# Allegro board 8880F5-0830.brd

Outline 581.66 x 429.26 mm; copper layers: TOP, L02_DGND, L03_SIGNAL, L04_DGND, L05_SIGNAL, L06_DGND, L07_SIGNAL, L08_DGND, L09_SIGNAL, L10_DGND, L11_POWER, L12_DGND, L13_POWER, L14_DGND, L15_POWER, L16_DGND, L17_5V, L18_CBIT, L19_DGND, L20_POWER, L21_DGND, L22_POWER, L23_DGND, L24_POWER, L25_DGND, L26_SIGNAL, L27_DGND, L28_SIGNAL, L29_DGND, L30_SIGNAL, L31_DGND, L32_SIGNAL, L33_DGND, BOTTOM. Coordinates in mm from the lower left corner of the outline.

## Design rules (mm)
net group DIFFPAIR0: nets D31702 D31704
net group DIFFPAIR1: nets D31706 D31708
net group DIFFPAIR2: nets D31710 D31712
net group DIFFPAIR3: nets D31714 D31716
net group DIFFPAIR4: nets D32102 D32104
net group DIFFPAIR5: nets D32106 D32108
net group DIFFPAIR6: nets D32110 D32112
net group DIFFPAIR7: nets D32114 D32116
net group DIFFPAIR8: nets D30102 D30104
net group DIFFPAIR9: nets D30106 D30108
net group DIFFPAIR10: nets D30110 D30112
net group DIFFPAIR11: nets D30114 D30116
net group DIFFPAIR12: nets D30502 D30504
net group DIFFPAIR13: nets D30506 D30508
net group DIFFPAIR14: nets D30510 D30512
net group DIFFPAIR15: nets D30514 D30516

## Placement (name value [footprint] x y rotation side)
BD29  BD120-3A-S8  [FB0805]  129.54 134.62 180 bottom
BD30  BD120-3A-S8  [FB0805]  129.54 146.05 180 bottom
BD31  BD120-3A-S8  [FB0805]  129.54 142.24 0 bottom
BD32  BD120-3A-S8  [FB0805]  513.08 238.76 180 bottom
BD33  BD120-3A-S8  [FB0805]  513.08 242.57 180 bottom
BD34  BD120-3A-S8  [FB0805]  453.64 145.54 0 bottom
BD35  BD120-3A-S8  [FB0805]  453.64 137.92 180 bottom
BD36  BD120-3A-S8  [FB0805]  129.54 138.43 180 bottom
BD37  BD120-3A-S8  [FB0805]  453.64 130.3 180 bottom
BD38  BD120-3A-S8  [FB0805]  513.08 242.57 180 bottom
BD39  BD120-3A-S8  [FB0805]  453.64 141.73 0 bottom
BD40  BD120-3A-S8  [FB0805]  453.64 134.11 180 bottom
BD41  BD120-3A-S8  [FB0805]  513.08 234.95 180 bottom
BD42  BD120-3A-S8  [FB0805]  513.08 231.14 180 bottom
BD43  BD120-3A-S8  [FB0805]  513.08 227.33 180 bottom
BD44  BD120-3A-S8  [FB0805]  129.54 149.86 180 bottom
BR902  330-1-S4  [R0402]  36.83 133.35 270 bottom
C3  0.1U-16-X-S4-MU  [C0402]  184.15 132.33 180 bottom
C4  0.1U-16-X-S4-MU  [C0402]  181.61 132.33 180 bottom
C5  22P-50-N-S4-AVX  [C0402]  221.21 277.48 90 bottom
C6  22P-50-N-S4-AVX  [C0402]  221.21 271.16 270 bottom
C7  0.1U-16-X-S4-MU  [C0402]  110.74 230.12 0 bottom
C8  0.1U-16-X-S4-MU  [C0402]  104.14 215.5 180 bottom
C9  0.1U-16-X-S4-MU  [C0402]  104.24 229.1 180 bottom
CA1  NC/10U-10-X6S-S6-MU  [C0603]  186.05 292.1 0 bottom
CA2  NC/47U-10-X5R-S8-TDK  [C0805]  186.16 294 0 bottom
CA3  NC/10U-10-X6S-S6-MU  [C0603]  174.62 292.1 180 bottom
CA4  NC/47U-10-X5R-S8-TDK  [C0805]  174.52 294 180 bottom
CA5  NC/10U-10-X6S-S6-MU  [C0603]  117.47 290.83 180 bottom
CA6  NC/47U-10-X5R-S8-TDK  [C0805]  117.37 292.74 180 bottom
CA7  NC/10U-10-X6S-S6-MU  [C0603]  169.54 292.1 0 bottom
CA8  NC/47U-10-X5R-S8-TDK  [C0805]  169.65 294 0 bottom
CA9  NC/10U-10-X6S-S6-MU  [C0603]  158.11 292.1 180 bottom
CA10  NC/47U-10-X5R-S8-TDK  [C0805]  158.01 294 180 bottom
CA11  NC/10U-10-X6S-S6-MU  [C0603]  186.05 275.59 0 bottom
CA12  NC/47U-10-X5R-S8-TDK  [C0805]  186.16 277.5 0 bottom
CA13  NC/47U-10-X5R-S8-TDK  [C0805]  202.16 294 0 bottom
CA14  NC/10U-10-X6S-S6-MU  [C0603]  202.06 292.1 0 bottom
CA15  NC/47U-10-X5R-S8-TDK  [C0805]  190.53 294 180 bottom
CA16  NC/10U-10-X6S-S6-MU  [C0603]  190.63 292.1 180 bottom
CA17  NC/47U-10-X5R-S8-TDK  [C0805]  169.65 277.5 0 bottom
CA18  NC/10U-10-X6S-S6-MU  [C0603]  169.54 275.59 0 bottom
CA19  NC/47U-10-X5R-S8-TDK  [C0805]  100.34 249.52 180 bottom
CA20  NC/10U-10-X6S-S6-MU  [C0603]  100.44 247.61 180 bottom
CA21  10U-10-X6S-S6-MU  [C0603]  186.05 289.56 0 bottom
CA22  10U-10-X6S-S6-MU  [C0603]  174.62 289.56 180 bottom
CA23  10U-10-X6S-S6-MU  [C0603]  117.47 288.29 180 bottom
CA24  10U-10-X6S-S6-MU  [C0603]  169.54 289.56 0 bottom
CA25  10U-10-X6S-S6-MU  [C0603]  158.11 289.56 180 bottom
CA26  10U-10-X6S-S6-MU  [C0603]  186.05 273.05 0 bottom
CA27  10U-10-X6S-S6-MU  [C0603]  202.06 289.56 0 bottom
CA28  10U-10-X6S-S6-MU  [C0603]  190.63 289.56 180 bottom
CA29  10U-10-X6S-S6-MU  [C0603]  169.54 273.05 0 bottom
CA30  NC/47U-10-X5R-S8-TDK  [C0805]  95.47 249.57 180 bottom
CA31  10U-10-X6S-S6-MU  [C0603]  95.57 247.66 180 bottom
CA32  NC/10U-10-X6S-S6-MU  [C0603]  202.06 275.59 0 bottom
CA33  NC/47U-10-X5R-S8-TDK  [C0805]  202.16 277.5 0 bottom
CA34  10U-10-X6S-S6-MU  [C0603]  202.06 273.05 0 bottom
CA35  NC/10U-10-X6S-S6-MU  [C0603]  174.62 275.59 180 bottom
CA36  NC/47U-10-X5R-S8-TDK  [C0805]  174.52 277.5 180 bottom
CA37  10U-10-X6S-S6-MU  [C0603]  174.62 273.05 180 bottom
CA38  NC/10U-10-X6S-S6-MU  [C0603]  158.11 275.59 180 bottom
CA39  NC/47U-10-X5R-S8-TDK  [C0805]  158.01 277.5 180 bottom
CA40  10U-10-X6S-S6-MU  [C0603]  158.11 273.05 180 bottom
CB1  0.1U-25-X-S6  [C0603]  116.84 130.81 0 bottom
CB2  10U-16-T-SA  [CODE_A]  116.84 128.27 0 bottom
CB3  0.1U-25-X-S6  [C0603]  472.44 130.81 0 bottom
CB4  10U-16-T-SA  [CODE_A]  472.44 128.27 0 bottom
CB5  0.1U-25-X-S6  [C0603]  556.51 300.99 0 bottom
CB6  10U-16-T-SA  [CODE_A]  556.51 298.45 0 bottom
CB7  0.1U-25-X-S6  [C0603]  223.52 298.45 0 bottom
CB8  10U-16-T-SA  [CODE_A]  223.52 295.91 0 bottom
CB9  0.1U-25-X-S6  [C0603]  23.01 130.71 0 bottom
CB10  10U-25-X7R-SA  [C1206]  22.86 128.27 0 bottom
CB11  0.1U-25-X-S6  [C0603]  484.02 130.71 0 bottom
CB12  10U-25-X7R-SA  [C1206]  483.87 128.27 0 bottom
CB13  0.1U-25-X-S6  [C0603]  547.52 300.89 0 bottom
CB14  10U-25-X7R-SA  [C1206]  547.37 298.45 0 bottom
CB15  0.1U-25-X-S6  [C0603]  12.45 262.13 0 bottom
CB16  10U-25-X7R-SA  [C1206]  12.3 259.69 0 bottom
CB19  0.1U-25-X7R-S4-MU  [C0402]  215.9 17.78 180 bottom
CC1  0.47U-10-X6S-S2-TY  [C0201]  237.98 224.12 90 bottom
CC2  4.7U-10-X6T-S4-MU  [C0402]  236.32 222.4 270 bottom
CC4  0.47U-10-X6S-S2-TY  [C0201]  229.81 247.93 0 bottom
CC6  0.47U-10-X6S-S2-TY  [C0201]  250.17 224.12 90 bottom
CC7  0.47U-10-X6S-S2-TY  [C0201]  229.81 246.66 0 bottom
CC8  0.47U-10-X6S-S2-TY  [C0201]  263.63 224.12 90 bottom
CC9  0.47U-10-X6S-S2-TY  [C0201]  254.61 266.16 270 bottom
CC11  0.47U-10-X6S-S2-TY  [C0201]  251.06 224.12 90 bottom
CC13  0.47U-10-X6S-S2-TY  [C0201]  256.77 224.12 90 bottom
CC15  4.7U-2.5-X6S-S2-MU  [C0201]  259.65 264.95 90 bottom
CC16  NC/4.7U-2.5-X6S-S2-MU  [C0201]  271.64 249.5 0 bottom
CC17  4.7U-2.5-X6S-S2-MU  [C0201]  229.81 253.69 0 bottom
CC19  0.47U-10-X6S-S2-TY  [C0201]  252.83 266.16 270 bottom
CC20  4.7U-10-X6T-S4-MU  [C0402]  254.11 267.66 0 bottom
CC22  0.47U-10-X6S-S2-TY  [C0201]  251.05 266.16 270 bottom
CC23  4.7U-10-X6T-S4-MU  [C0402]  250.34 253.09 270 bottom
CC25  0.47U-10-X6S-S2-TY  [C0201]  272.85 245.18 180 bottom
CC26  0.47U-10-X6S-S2-TY  [C0201]  253.72 266.16 270 bottom
CC27  0.47U-10-X6S-S2-TY  [C0201]  272.85 249.5 180 bottom
CC28  0.47U-10-X6S-S2-TY  [C0201]  259.65 266.16 270 bottom
CC29  0.47U-10-X6S-S2-TY  [C0201]  231.03 253.69 180 bottom
CC30  0.47U-10-X6S-S2-TY  [C0201]  229.81 243.41 0 bottom
CC31  0.47U-10-X6S-S2-TY  [C0201]  249.28 224.12 90 bottom
CC32  0.47U-10-X6S-S2-TY  [C0201]  262.36 224.12 90 bottom
CC33  0.47U-10-X6S-S2-TY  [C0201]  272.85 243.91 180 bottom
CC34  0.47U-10-X6S-S2-TY  [C0201]  251.94 266.16 270 bottom
CC35  0.47U-10-X6S-S2-TY  [C0201]  272.85 241.37 180 bottom
CC36  0.47U-10-X6S-S2-TY  [C0201]  272.85 242.64 180 bottom
CC37  0.47U-10-X6S-S2-TY  [C0201]  247.57 264.95 90 bottom
CC38  NC/4.7U-2.5-X6S-S2-MU  [C0201]  247.57 266.16 270 bottom
CC39  0.47U-10-X6S-S2-TY  [C0201]  231.03 249.2 180 bottom
CC40  4.7U-2.5-X6S-S2-MU  [C0201]  258.5 246.67 180 bottom
CC41  4.7U-2.5-X6S-S2-MU  [C0201]  229.81 249.2 0 bottom
CC42  4.7U-2.5-X6S-S2-MU  [C0201]  251.54 253.03 90 bottom
CD1  0.1U-10-X7R-S2-MU  [C0201]  237.98 225.34 270 top
CD3  0.1U-10-X7R-S2-MU  [C0201]  271.64 241.37 0 top
CD4  0.1U-10-X7R-S2-MU  [C0201]  254.61 264.95 90 top
CD5  0.1U-10-X7R-S2-MU  [C0201]  263.63 225.34 270 top
CD6  0.1U-10-X7R-S2-MU  [C0201]  231.03 246.66 180 top
CD7  0.1U-10-X7R-S2-MU  [C0201]  271.64 242.64 0 top
CD8  0.1U-10-X7R-S2-MU  [C0201]  251.06 225.34 270 top
CD9  0.1U-10-X7R-S2-MU  [C0201]  256.77 225.34 270 top
CD10  0.1U-10-X7R-S2-MU  [C0201]  271.64 249.5 0 top
CD11  0.1U-10-X7R-S2-MU  [C0201]  259.65 264.95 90 top
CD12  0.1U-10-X7R-S2-MU  [C0201]  231.03 253.69 180 top
CD13  0.1U-10-X7R-S2-MU  [C0201]  252.83 264.95 90 top
CD14  0.1U-10-X7R-S2-MU  [C0201]  251.05 264.95 90 top
CD15  0.1U-10-X7R-S2-MU  [C0201]  271.64 245.18 0 top
CD16  0.1U-10-X7R-S2-MU  [C0201]  253.72 264.95 90 top
CD17  0.1U-10-X7R-S2-MU  [C0201]  231.03 247.93 180 top
CD18  0.1U-10-X7R-S2-MU  [C0201]  251.94 264.95 90 top
CD19  0.1U-10-X7R-S2-MU  [C0201]  231.03 243.41 180 top
CD20  0.1U-10-X7R-S2-MU  [C0201]  271.64 243.91 0 top
CD21  0.1U-10-X7R-S2-MU  [C0201]  262.36 225.34 270 top
CD22  0.1U-10-X7R-S2-MU  [C0201]  249.28 225.34 270 top
CD23  0.1U-10-X7R-S2-MU  [C0201]  250.17 225.34 270 top
CD24  0.1U-10-X7R-S2-MU  [C0201]  247.57 264.95 90 top
CD25  0.1U-10-X7R-S2-MU  [C0201]  231.03 249.2 180 top
CSDPS225  V93K_CSDPS_DPS32  [PG_VG93K_PF_DPS32_G8D225]  254 331.47 0 top
CSDPS229  V93K_CSDPS_DPS32  [PG_VG93K_PF_DPS32_G8D229]  180.34 331.47 0 top
CSDPS425  V93K_CSDPS_DPS32  [PG_VG93K_PF_DPS32_G8D425]  254 341.63 0 top
CSDPS429  V93K_CSDPS_DPS32  [PG_VG93K_PF_DPS32_G8D429]  180.34 341.63 0 top
D101/D501  V93K_PS1600 HD  [PG_VG93K_F_HSM_G1D101_501_ND]  327.66 97.79 0 top
D102  V93K_CH  [PG_VG93K_F_G1D102]  327.66 77.47 0 top
D103  V93K_CH  [PG_VG93K_F_G1D103]  327.66 57.15 0 top
D104  V93K_CH  [PG_VG93K_F_G1D104]  327.66 36.83 0 top
D105/D505  V93K_PS1600 HD  [PG_VG93K_F_HSM_G1D105_505_ND]  401.32 97.79 0 top
D106  V93K_CH  [PG_VG93K_F_G1D106]  401.32 77.47 0 top
D107  V93K_CH  [PG_VG93K_F_G1D107]  401.32 57.15 0 top
D108  V93K_CH  [PG_VG93K_F_G1D108]  401.32 36.83 0 top
D109  V93K_CH  [PG_VG93K_F_G2D109]  401.32 331.47 0 top
D110  V93K_CH  [PG_VG93K_F_G2D110]  401.32 351.79 0 top
D111  V93K_CH  [PG_VG93K_F_G2D111]  401.32 372.11 0 top
D112  V93K_CH  [PG_VG93K_F_G2D112]  401.32 392.43 0 top
D113  V93K_CH  [PG_VG93K_F_G2D113]  327.66 331.47 0 top
D114  V93K_CH  [PG_VG93K_F_G2D114]  327.66 351.79 0 top
D115  V93K_CH  [PG_VG93K_F_G2D115]  327.66 372.11 0 top
D116  V93K_CH  [PG_VG93K_F_G2D116]  327.66 392.43 0 top
D117/D517  V93K_PS1600 HD  [PG_VG93K_F_HSM_G3D117_517_ND]  180.34 97.79 0 top
D118  V93K_CH  [PG_VG93K_F_G3D118]  180.34 77.47 0 top
D119  V93K_CH  [PG_VG93K_F_G3D119]  180.34 57.15 0 top
D120  V93K_CH  [PG_VG93K_F_G3D120]  180.34 36.83 0 top
D121/D521  V93K_PS1600 HD  [PG_VG93K_F_HSM_G3D121_521_ND]  254 97.79 0 top
D122  V93K_CH  [PG_VG93K_F_G3D122]  254 77.47 0 top
D123  V93K_CH  [PG_VG93K_F_G3D123]  254 57.15 0 top
D124  V93K_CH  [PG_VG93K_F_G3D124]  254 36.83 0 top
D125  V93K_CH  [PG_VG93K_F_G4D125]  33.02 97.79 0 top
D126  V93K_CH  [PG_VG93K_F_G4D126]  33.02 77.47 0 top
D127  V93K_CH  [PG_VG93K_F_G4D127]  33.02 57.15 0 top
D128  V93K_CH  [PG_VG93K_F_G4D128]  33.02 36.83 0 top
D129  V93K_CH  [PG_VG93K_F_G4D129]  106.68 97.79 0 top
D130  V93K_CH  [PG_VG93K_F_G4D130]  106.68 77.47 0 top
D131  V93K_CH  [PG_VG93K_F_G4D131]  106.68 57.15 0 top
D132  V93K_CH  [PG_VG93K_F_G4D132]  106.68 36.83 0 top
D231  V93K_CH  [PG_VG93K_F_G8D231]  180.34 372.11 0 top
D301  V93K_CH  [PG_VG93K_F_G1D301]  327.66 87.63 0 top
D302  V93K_CH  [PG_VG93K_F_G1D302]  327.66 67.31 0 top
D305  V93K_CH  [PG_VG93K_F_G1D305]  401.32 87.63 0 top
D306  V93K_CH  [PG_VG93K_F_G1D306]  401.32 67.31 0 top
D309  V93K_PSSL  [PG_VG93K_F_PSSL_G2D309_ND]  401.32 341.63 0 top
D313  V93K_PSSL  [PG_VG93K_F_PSSL_G2D313_ND]  327.66 341.63 0 top
D317  V93K_CH  [PG_VG93K_F_G3D317]  180.34 87.63 0 top
D318  V93K_CH  [PG_VG93K_F_G3D318]  180.34 67.31 0 top
D321  V93K_CH  [PG_VG93K_F_G3D321]  254 87.63 0 top
D322  V93K_CH  [PG_VG93K_F_G3D322]  254 67.31 0 top
D431  V93K_CH  [PG_VG93K_F_G8D431]  180.34 382.27 0 top
DPS1  V93K_DPS  [PG_VG93K_F_G1DPS1]  401.32 16.51 0 top
DPS2  V93K_DPS  [PG_VG93K_F_G2DPS2]  327.66 412.75 0 top
DPS3  V93K_DPS  [PG_VG93K_F_G3DPS3]  254 16.51 0 top
DPS8  V93K_DPS  [PG_VG93K_F_G8DPS8]  180.34 412.75 0 top
FD1  -  [FD_040_V2]  159.82 131.98 0 top
FD2  -  [FD_040_V2]  423.24 131.98 0 top
FD3  -  [FD_040_V2]  423.24 297.28 0 top
FD4  -  [FD_040_V2]  156.51 297.46 0 top
FD5  -  [FD_040_V2]  159.82 131.98 180 bottom
FD6  -  [FD_040_V2]  423.24 131.98 180 bottom
FD7  -  [FD_040_V2]  423.24 297.28 180 bottom
FD8  -  [FD_040_V2]  156.51 297.46 180 bottom
FD9  -  [FD_040_V2]  570.23 128.27 180 bottom
FD10  -  [FD_040_V2]  570.23 300.99 0 top
FD11  -  [FD_040_V2]  570.23 300.99 180 bottom
FD12  -  [FD_040_V2]  11.43 300.99 0 top
FD13  -  [FD_040_V2]  11.43 300.99 180 bottom
FD14  -  [FD_040_V2]  11.43 127 0 top
FD15  -  [FD_040_V2]  11.43 127 180 bottom
FD16  -  [FD_040_V2]  570.23 128.27 0 top
GND1  TP01  [TP_040_T]  173.57 294 0 top
GND2  TP01  [TP_040_T]  187.11 294 180 top
GND3  TP01  [TP_040_T]  116.42 292.74 0 top
GND4  TP01  [TP_040_T]  157.06 294 0 top
GND5  TP01  [TP_040_T]  170.6 294 180 top
GND6  TP01  [TP_040_T]  173.57 277.5 0 top
GND7  TP01  [TP_040_T]  203.11 294 180 top
GND8  TP01  [TP_040_T]  189.58 294 0 top
GND9  TP01  [TP_040_T]  170.6 277.5 180 top
GND10  TP01  [TP_040_T]  99.36 249.46 0 top
GND11  TP01  [TP_040_T]  94.49 249.52 0 top
GND12  TP01  [TP_040_T]  203.11 277.5 180 top
GND13  TP01  [TP_040_T]  187.11 277.5 180 top
GND14  TP01  [TP_040_T]  157.06 277.5 0 top
HX8880-F05  REF-CODE-CHIP  [CHIP_CODE]  559.05 279.65 0 top
J1  HDR-2X1-M  [JP_2P_100]  110.24 232.41 270 bottom
J2  HDR-3X1-M  [JP_3P_100]  88.76 205.43 90 bottom
J3  HDR-3X1-M  [JP_3P_100]  88.76 219.15 90 bottom
J4  HDR-2X1-M  [JP_2P_100]  96.27 231.39 90 bottom
J5  HDR-2X1-M  [JP_2P_100]  96.27 243.08 90 bottom
JG_220919AA01  REF-CODE-SOCKET  [SOCKET_CODE]  559.05 284.73 0 top
JG_220919AA02  REF-CODE-SOCKET  [SOCKET_CODE]  559.05 287.27 0 top
K1  G6K-2F-RF-T-5V-SPECIAL  [RL_G6K2FRT_8P_5V_GR]  347.73 292.86 0 bottom
K2  G6K-2F-RF-T-5V-SPECIAL  [RL_G6K2FRT_8P_5V_GR]  334.26 292.86 0 bottom
K3  G6K-2F-RF-T-5V-SPECIAL  [RL_G6K2FRT_8P_5V_GR]  320.8 292.86 0 bottom
K4  G6K-2F-RF-T-5V-SPECIAL  [RL_G6K2FRT_8P_5V_GR]  289.56 276.1 180 bottom
K5  G6K-2F-RF-T-5V-SPECIAL  [RL_G6K2FRT_8P_5V_GR]  307.59 292.86 0 bottom
K6  G6K-2F-RF-T-5V-SPECIAL  [RL_G6K2FRT_8P_5V_GR]  294.39 292.86 0 bottom
K7  G6K-2F-RF-T-5V-SPECIAL  [RL_G6K2FRT_8P_5V_GR]  280.92 292.86 0 bottom
K8  G6K-2F-RF-T-5V-SPECIAL  [RL_G6K2FRT_8P_5V_GR]  267.46 292.86 0 bottom
K9  UA2-5NJ-A-V3  [RL_NECUA2_5V_V3]  219.96 235.46 90 bottom
K10  UA2-5NJ-A-V3  [RL_NECUA2_5V_V3]  111.76 237.24 0 bottom
K11  G6K-2F-RF-T-5V-SPECIAL  [RL_G6K2FRT_8P_5V_GR]  254.25 292.86 0 bottom
K12  UA2-5NJ-A-V3  [RL_NECUA2_5V_V3]  219.96 246.89 90 bottom
K13  UA2-5NJ-A-V3  [RL_NECUA2_5V_V3]  123.7 229.62 180 bottom
K14  UA2-5NJ-A-V3  [RL_NECUA2_5V_V3]  112.01 220.73 180 bottom
K15  UA2-5NJ-A-V3  [RL_NECUA2_5V_V3]  123.99 213.19 180 bottom
K16  G6K-2F-RF-T-5V-SPECIAL  [RL_G6K2FRT_8P_5V_GR]  241.05 292.61 180 bottom
K17  G6K-2F-RF-T-5V-SPECIAL  [RL_G6K2FRT_8P_5V_GR]  188.47 260.35 270 bottom
K18  UB2-5NU-B  [RL_NECUB2_5V]  228.45 274.32 0 bottom
K19  UA2-5NJ-A-V3  [RL_NECUA2_5V_V3]  112.01 213.11 180 bottom
K20  UA2-5NJ-A-V3  [RL_NECUA2_5V_V3]  123.95 220.73 180 bottom
K21  G6K-2F-RF-T-5V-SPECIAL  [RL_G6K2FRT_8P_5V_GR]  204.98 260.35 270 bottom
K22  G6K-2F-RF-T-5V-SPECIAL  [RL_G6K2FRT_8P_5V_GR]  205.23 232.92 270 bottom
K23  G6K-2F-RF-T-5V-SPECIAL  [RL_G6K2FRT_8P_5V_GR]  171.7 219.2 270 bottom
K24  G6K-2F-RF-T-5V-SPECIAL  [RL_G6K2FRT_8P_5V_GR]  188.47 232.92 270 bottom
K25  G6K-2F-RF-T-5V-SPECIAL  [RL_G6K2FRT_8P_5V_GR]  205.23 246.63 270 bottom
K26  G6K-2F-RF-T-5V-SPECIAL  [RL_G6K2FRT_8P_5V_GR]  171.7 232.92 270 bottom
K27  G6K-2F-RF-T-5V-SPECIAL  [RL_G6K2FRT_8P_5V_GR]  188.47 246.63 270 bottom
K28  UA2-5NJ-A-V3  [RL_NECUA2_5V_V3]  100.33 237.24 0 bottom
K29  G6K-2F-RF-T-5V-SPECIAL  [RL_G6K2FRT_8P_5V_GR]  171.7 260.35 270 bottom
K30  G6K-2F-RF-T-5V-SPECIAL  [RL_G6K2FRT_8P_5V_GR]  171.7 246.63 270 bottom
K31  EC2-5NJ-A  [RL_NECEC2_10P_5V]  196.34 276.86 90 bottom
K33  NC/UA2-5NJ-A-V3  [RL_NECUA2_5V_V3]  123.7 237.24 180 bottom
K34  EC2-5NJ-A  [RL_NECEC2_10P_5V]  180.34 293.37 90 bottom
K36  EC2-5NJ-A  [RL_NECEC2_10P_5V]  123.19 292.1 90 bottom
K37  EC2-5NJ-A  [RL_NECEC2_10P_5V]  163.83 293.37 90 bottom
K39  EC2-5NJ-A  [RL_NECEC2_10P_5V]  180.34 276.86 90 bottom
K40  EC2-5NJ-A  [RL_NECEC2_10P_5V]  196.34 293.37 90 bottom
K42  EC2-5NJ-A  [RL_NECEC2_10P_5V]  163.83 276.86 90 bottom
K43  G6K-2F-RF-T-5V-SPECIAL  [RL_G6K2FRT_8P_5V_GR]  269.49 276.1 180 bottom
LD902  LDG-2-S8  [LED_0805]  36.83 130.81 90 top
LOGO1  -  [LOGO_KT_KSMT]  538.48 154.94 0 top
LOGO2  LOGO_HX_Himax  [LOGO_HX_HIMAX]  518.16 138.43 0 top
LQFP176-20X20-P0.4  REF-CODE-CHIP  [CHIP_CODE]  559.05 282.19 0 top
NOREF  -  []  331.86 192.43 90 top
NOREF#2  -  []  110.21 222.33 0 top
NOREF#3  -  []  247.89 204.35 90 top
NOREF#4  -  []  414.82 281.37 0 top
NOREF#5  -  []  473.7 219.66 90 top
NOREF#6  -  []  352.55 185.18 0 top
NOREF#7  -  []  451.64 179.06 0 top
NOREF#8  -  []  201.49 161 90 top
NOREF#9  -  []  375.73 193.43 0 top
NOREF#10  -  []  383.09 257.11 0 top
NOREF#11  -  []  256.77 165.04 90 top
NOREF#12  -  []  402.14 146.88 0 top
NOREF#13  -  []  184.47 159.65 90 top
NOREF#14  -  []  290.64 288.86 0 top
NOREF#15  -  []  399.67 131.89 0 top
NOREF#16  -  []  272.24 249.18 90 top
NOREF#17  -  []  230.41 188.88 90 top
NOREF#18  -  []  118.7 182.93 90 top
NOREF#19  -  []  201.23 219.75 90 top
NOREF#20  -  []  456.04 179.06 0 top
NOREF#21  -  []  230.83 164.63 0 top
NOREF#22  -  []  112.67 178.64 0 top
NOREF#23  -  []  339.65 264.65 90 top
NOREF#24  -  []  259.65 205.86 90 top
NOREF#25  -  []  312.46 131.69 90 top
NOREF#26  -  []  211.11 160.4 90 top
NOREF#27  -  []  274.37 147.93 90 top
NOREF#28  -  []  229.05 211.67 0 top
NOREF#29  -  []  201.23 242.78 90 top
NOREF#30  -  []  554.86 298.45 0 top
NOREF#31  -  []  329.85 164.74 0 top
NOREF#32  -  []  331.94 205.86 90 top
NOREF#33  -  []  175.8 228.97 90 top
NOREF#34  -  []  192.47 175.56 90 top
NOREF#35  -  []  310.73 249.2 0 top
NOREF#36  -  []  201.4 254.6 90 top
NOREF#37  -  []  229.05 271.67 0 top
NOREF#38  -  []  309.51 186.66 0 top
NOREF#39  -  []  262.68 163.52 90 top
NOREF#40  -  []  224.65 211.67 0 top
NOREF#41  -  []  279.7 155.38 0 top
NOREF#42  -  []  237.66 164.74 0 top
NOREF#43  -  []  463.61 171.53 0 top
NOREF#44  -  []  209.49 168.6 90 top
NOREF#45  -  []  378.33 217.11 0 top
NOREF#46  -  []  394.05 287.22 0 top
NOREF#47  -  []  259.97 264.35 90 top
NOREF#48  -  []  518.38 276.41 90 top
NOREF#49  -  []  310.43 188.88 90 top
NOREF#50  -  []  289.01 272.1 0 top
NOREF#51  -  []  167.7 134.07 90 top
NOREF#52  -  []  256.45 224.74 0 top
NOREF#53  -  []  268.01 296.86 0 top
NOREF#54  -  []  346.08 288.86 0 top
NOREF#55  -  []  383.09 241.11 0 top
NOREF#56  -  []  253.33 241.33 90 top
NOREF#57  -  []  352.55 241.37 0 top
NOREF#58  -  []  119.99 214.79 0 top
NOREF#59  -  []  331.62 265.56 90 top
NOREF#60  -  []  272.25 184.86 90 top
NOREF#61  -  []  330.74 164.72 0 top
NOREF#62  -  []  336.77 225.04 90 top
NOREF#63  -  []  240.94 151.63 90 top
NOREF#64  -  []  456.08 239.34 0 top
NOREF#65  -  []  182.57 240.28 90 top
NOREF#66  -  []  165.8 199.39 0 top
NOREF#67  -  []  201.23 204.09 90 top
NOREF#68  -  []  400.85 281.11 0 top
NOREF#69  -  []  304.82 146.05 0 top
NOREF#70  -  []  308.91 139.64 0 top
NOREF#71  -  []  459.28 236.14 0 top
NOREF#72  -  []  104.18 191.95 90 top
NOREF#73  -  []  287.27 286.96 90 top
NOREF#74  -  []  258.2 186.67 0 top
NOREF#75  -  []  257.9 186.35 90 top
NOREF#76  -  []  410.84 163.64 90 top
NOREF#77  -  []  226.85 271.67 0 top
NOREF#78  -  []  461.96 217.98 0 top
NOREF#79  -  []  253.72 265.86 90 top
NOREF#80  -  []  310.43 249.52 0 top
NOREF#81  -  []  329.28 225.04 90 top
NOREF#82  -  []  229.51 246.66 0 top
NOREF#83  -  []  317.57 269.63 90 top
NOREF#84  -  []  182.57 144.78 0 top
NOREF#85  -  []  471.21 219.38 90 top
NOREF#86  -  []  230.41 247.61 90 top
NOREF#87  -  []  184.47 145.93 90 top
NOREF#88  -  []  252.51 265.56 90 top
NOREF#89  -  []  384.59 162.84 90 top
NOREF#90  -  []  209.49 150.83 90 top
NOREF#91  -  []  331.06 223.82 90 top
NOREF#92  -  []  387.39 249.11 0 top
NOREF#93  -  []  327.25 264.35 90 top
NOREF#94  -  []  396.55 225.11 0 top
NOREF#95  -  []  167.7 201.89 90 top
NOREF#96  -  []  237.83 197.63 0 top
NOREF#97  -  []  319.15 296.86 0 top
NOREF#98  -  []  201.23 214 0 top
NOREF#99  -  []  399.67 139.89 0 top
NOREF#100  -  []  254.29 205.56 0 top
NOREF#101  -  []  393.19 287.22 90 top
NOREF#102  -  []  199.84 148.65 90 top
NOREF#103  -  []  319.15 288.86 0 top
NOREF#104  -  []  310.43 193.37 0 top
NOREF#105  -  []  166.06 189.04 90 top
NOREF#106  -  []  341.63 195.43 90 top
NOREF#107  -  []  96.58 195.15 0 top
NOREF#108  -  []  222.67 298 90 top
NOREF#109  -  []  394.05 223.21 0 top
NOREF#110  -  []  344.37 128.27 90 top
NOREF#111  -  []  172.08 272.6 90 top
NOREF#112  -  []  331.62 205.56 90 top
NOREF#113  -  []  260.6 286.96 90 top
NOREF#114  -  []  184.89 213.45 90 top
NOREF#115  -  []  389.7 209.36 0 top
NOREF#116  -  []  398.65 233.11 0 top
NOREF#117  -  []  390.34 192.28 0 top
NOREF#118  -  []  411.99 161.74 90 top
NOREF#119  -  []  184.47 149.48 90 top
NOREF#120  -  []  352.55 183.91 0 top
NOREF#121  -  []  259.59 145.09 0 top
NOREF#122  -  []  185.2 290.01 90 top
NOREF#123  -  []  465.45 292.92 90 top
NOREF#124  -  []  377.23 224.65 90 top
NOREF#125  -  []  199.59 216.47 90 top
NOREF#126  -  []  471.59 130.36 90 top
NOREF#127  -  []  298.13 214.06 0 top
NOREF#128  -  []  272.8 157.28 0 top
NOREF#129  -  []  201.23 187.92 90 top
NOREF#130  -  []  473.79 196.21 0 top
NOREF#131  -  []  327.25 205.56 0 top
NOREF#132  -  []  342.36 223.82 90 top
NOREF#133  -  []  415.6 146.88 0 top
NOREF#134  -  []  339.33 205.55 0 top
NOREF#135  -  []  230.43 243.09 0 top
NOREF#136  -  []  400.79 154.88 0 top
NOREF#137  -  []  352.25 184.23 0 top
NOREF#138  -  []  331.86 252.43 90 top
NOREF#139  -  []  460.93 234.74 90 top
NOREF#140  -  []  352.24 249.18 90 top
NOREF#141  -  []  167.7 138.47 90 top
NOREF#142  -  []  106.76 217.73 90 top
NOREF#143  -  []  188.08 289.11 90 top
NOREF#144  -  []  115.36 235.64 0 top
NOREF#145  -  []  479.44 239.09 0 top
NOREF#146  -  []  184.89 145.38 90 top
NOREF#147  -  []  342.68 223.52 90 top
NOREF#148  -  []  184.47 159.65 0 top
NOREF#149  -  []  403.99 180.15 0 top
NOREF#150  -  []  352.93 288.86 90 top
NOREF#151  -  []  468.85 257.36 90 top
NOREF#152  -  []  167.7 192.32 90 top
NOREF#153  -  []  272.25 241.69 0 top
NOREF#154  -  []  237.66 164.72 0 top
NOREF#155  -  []  252.51 205.56 90 top
NOREF#156  -  []  120.21 178.64 0 top
NOREF#157  -  []  351.04 189.82 0 top
NOREF#158  -  []  404.4 289.17 90 top
NOREF#159  -  []  230.43 253.37 0 top
NOREF#160  -  []  230.43 247.61 90 top
NOREF#161  -  []  461.86 182.17 90 top
NOREF#162  -  []  374.08 195.9 90 top
NOREF#163  -  []  201.23 231.27 90 top
NOREF#164  -  []  331.62 265.55 0 top
NOREF#165  -  []  108.01 222.33 0 top
NOREF#166  -  []  251.06 165.04 90 top
NOREF#167  -  []  327.57 264.65 90 top
NOREF#168  -  []  419.9 288.57 90 top
NOREF#169  -  []  230.41 243.09 90 top
NOREF#170  -  []  320.94 211.63 90 top
NOREF#171  -  []  420.62 271.47 90 top
NOREF#172  -  []  343.83 171.63 90 top
NOREF#173  -  []  465.81 171.53 0 top
NOREF#174  -  []  392.24 194.78 90 top
NOREF#175  -  []  230.83 224.63 0 top
NOREF#176  -  []  310.73 247.93 0 top
NOREF#177  -  []  192.57 201.79 90 top
NOREF#178  -  []  468.01 222.58 0 top
NOREF#179  -  []  235.85 288.61 90 top
NOREF#180  -  []  399.8 207.46 90 top
NOREF#181  -  []  373.83 192.28 0 top
NOREF#182  -  []  425.2 161.74 90 top
NOREF#183  -  []  124.39 214.79 0 top
NOREF#184  -  []  250.74 224.74 0 top
NOREF#185  -  []  310.41 243.09 90 top
NOREF#186  -  []  259.33 205.56 90 top
NOREF#187  -  []  298.16 248.49 0 top
NOREF#188  -  []  317.98 223.82 90 top
NOREF#189  -  []  239.33 236.03 90 top
NOREF#190  -  []  377.48 273.16 90 top
NOREF#191  -  []  241.82 167.13 90 top
NOREF#192  -  []  518.38 259.9 90 top
NOREF#193  -  []  230.43 183.09 0 top
NOREF#194  -  []  384.59 179.7 90 top
NOREF#195  -  []  460.93 191.31 90 top
NOREF#196  -  []  310.41 186.34 90 top
NOREF#197  -  []  230.73 249.2 0 top
NOREF#198  -  []  229.21 247.61 0 top
NOREF#199  -  []  175.7 137.37 90 top
NOREF#200  -  []  309.21 243.09 0 top
NOREF#201  -  []  327.25 265.56 0 top
NOREF#202  -  []  229.51 187.93 0 top
NOREF#203  -  []  88.64 247.45 90 top
NOREF#204  -  []  310.41 247.61 90 top
NOREF#205  -  []  254.61 204.65 90 top
NOREF#206  -  []  247.25 265.55 0 top
NOREF#207  -  []  235.4 289.88 90 top
NOREF#208  -  []  460.89 217.9 90 top
NOREF#209  -  []  397.57 131.89 0 top
NOREF#210  -  []  371.73 289.12 0 top
NOREF#211  -  []  400.34 194.68 90 top
NOREF#212  -  []  262.09 143.19 0 top
NOREF#213  -  []  399.99 164.91 90 top
NOREF#214  -  []  322.23 233.13 0 top
NOREF#215  -  []  352.25 184.86 90 top
NOREF#216  -  []  383.09 273.11 0 top
NOREF#217  -  []  390.94 273.16 90 top
NOREF#218  -  []  230.43 248.88 0 top
NOREF#219  -  []  451.68 186.77 0 top
NOREF#220  -  []  246.63 130.24 90 top
NOREF#221  -  []  184.89 240.88 90 top
NOREF#222  -  []  459.28 183.57 0 top
NOREF#223  -  []  459.28 211.76 90 top
NOREF#224  -  []  239.4 296.61 0 top
NOREF#225  -  []  310.83 164.63 0 top
NOREF#226  -  []  251.62 264.35 90 top
NOREF#227  -  []  201.23 192.32 90 top
NOREF#228  -  []  155.57 275.14 90 top
NOREF#229  -  []  263.95 164.74 90 top
NOREF#230  -  []  309.21 188.88 0 top
NOREF#231  -  []  249.28 163.82 90 top
NOREF#232  -  []  343.63 163.82 90 top
NOREF#233  -  []  106.11 234.24 0 top
NOREF#234  -  []  377.23 241.16 90 top
NOREF#235  -  []  177.33 255.9 90 top
NOREF#236  -  []  229.51 249.2 0 top
NOREF#237  -  []  166.06 135.19 90 top
NOREF#238  -  []  251.62 265.55 0 top
NOREF#239  -  []  318.32 131.64 0 top
NOREF#240  -  []  406.65 271.21 90 top
NOREF#241  -  []  393.74 131.44 90 top
NOREF#242  -  []  75.98 287.84 90 top
NOREF#243  -  []  413.2 164.91 90 top
NOREF#244  -  []  209.23 236.67 90 top
NOREF#245  -  []  346.08 296.86 0 top
NOREF#246  -  []  392.47 272.56 90 top
NOREF#247  -  []  118.7 188.08 0 top
NOREF#248  -  []  166.06 257.62 90 top
NOREF#249  -  []  167.7 151.68 90 top
NOREF#250  -  []  396.55 289.12 0 top
NOREF#251  -  []  209.23 189.02 90 top
NOREF#252  -  []  192.47 257.6 90 top
NOREF#253  -  []  327.25 265.55 0 top
NOREF#254  -  []  310.43 183.09 90 top
NOREF#255  -  []  352.55 181.37 0 top
NOREF#256  -  []  319.33 236.03 90 top
NOREF#257  -  []  374.88 217.11 0 top
NOREF#258  -  []  334.29 205.56 0 top
NOREF#259  -  []  272.25 242.96 0 top
NOREF#260  -  []  387.39 232.85 0 top
NOREF#261  -  []  417.7 154.88 0 top
NOREF#262  -  []  461.86 230.75 0 top
NOREF#263  -  []  128.05 271.33 90 top
NOREF#264  -  []  167.7 206.29 90 top
NOREF#265  -  []  333.4 265.55 0 top
NOREF#266  -  []  309.51 246.66 0 top
NOREF#267  -  []  256.45 164.72 0 top
NOREF#268  -  []  373.87 171.39 0 top
NOREF#269  -  []  209.23 202.99 90 top
NOREF#270  -  []  230.41 248.88 90 top
NOREF#271  -  []  228.36 262.16 45 top
NOREF#272  -  []  342.36 163.82 90 top
NOREF#273  -  []  194.09 228.47 90 top
NOREF#274  -  []  175.8 256.4 90 top
NOREF#275  -  []  127.3 235.64 90 top
NOREF#276  -  []  352.55 243.91 0 top
NOREF#277  -  []  241.82 227.13 90 top
NOREF#278  -  []  167.7 159.65 90 top
NOREF#279  -  []  272.25 182.32 90 top
NOREF#280  -  []  263.14 282 0 top
NOREF#281  -  []  110.21 214.71 0 top
NOREF#282  -  []  221.56 242.89 0 top
NOREF#283  -  []  378.33 241.11 90 top
NOREF#284  -  []  333.4 205.56 90 top
NOREF#285  -  []  251.54 252.73 90 top
NOREF#286  -  []  247.25 205.56 90 top
NOREF#287  -  []  300.01 288.41 90 top
NOREF#288  -  []  419.9 154.88 0 top
NOREF#289  -  []  84.04 287.84 90 top
NOREF#290  -  []  165.8 144.78 90 top
NOREF#291  -  []  201.91 159.1 90 top
NOREF#292  -  []  124.61 178.64 0 top
NOREF#293  -  []  411.26 209.66 90 top
NOREF#294  -  []  385.19 224.85 0 top
NOREF#295  -  []  399.07 208.91 90 top
NOREF#296  -  []  247.78 140.14 0 top
NOREF#297  -  []  379.52 188.15 0 top
NOREF#298  -  []  404.15 225.11 0 top
NOREF#299  -  []  286.55 288.41 90 top
NOREF#300  -  []  182.57 254 0 top
NOREF#301  -  []  182.57 240.28 0 top
NOREF#302  -  []  272.24 182.32 90 top
NOREF#303  -  []  209.33 215.25 90 top
NOREF#304  -  []  167.7 190.12 90 top
NOREF#305  -  []  210.86 228.47 90 top
NOREF#306  -  []  262.68 224.74 90 top
NOREF#307  -  []  424.05 163.64 90 top
NOREF#308  -  []  423.61 182.42 90 top
NOREF#309  -  []  238.3 223.52 90 top
NOREF#310  -  []  393.19 255.21 90 top
NOREF#311  -  []  478.57 257.36 90 top
NOREF#312  -  []  285.02 288.91 90 top
NOREF#313  -  []  192.57 147.18 90 top
NOREF#314  -  []  168.13 199.99 90 top
NOREF#315  -  []  119.95 195.15 0 top
NOREF#316  -  []  247.57 204.65 90 top
NOREF#317  -  []  281.47 296.86 0 top
NOREF#318  -  []  460.93 166.93 90 top
NOREF#319  -  []  408.02 271.47 0 top
NOREF#320  -  []  272.24 243.59 90 top
NOREF#321  -  []  402.06 217.61 0 top
NOREF#322  -  []  419.9 288.67 90 top
NOREF#323  -  []  272.25 249.18 90 top
NOREF#324  -  []  118.74 215.34 0 top
NOREF#325  -  []  242.23 233.13 90 top
NOREF#326  -  []  463.11 186.77 0 top
NOREF#327  -  []  317.05 288.86 0 top
NOREF#328  -  []  333.4 265.56 90 top
NOREF#329  -  []  209.23 222.95 90 top
NOREF#330  -  []  456.08 186.77 0 top
NOREF#331  -  []  249.6 163.52 90 top
NOREF#332  -  []  410.52 289.12 0 top
NOREF#333  -  []  412.62 297.12 0 top
NOREF#334  -  []  252.83 204.65 90 top
NOREF#335  -  []  330.73 265.56 90 top
NOREF#336  -  []  252.51 205.56 0 top
NOREF#337  -  []  119.7 231.22 0 top
NOREF#338  -  []  304.61 131.64 0 top
NOREF#339  -  []  217.41 213.24 90 top
NOREF#340  -  []  408.02 239.21 0 top
NOREF#341  -  []  155.57 291.65 90 top
NOREF#342  -  []  165.8 254 0 top
NOREF#343  -  []  165.8 199.39 90 top
NOREF#344  -  []  329.85 224.74 0 top
NOREF#345  -  []  378.58 289.12 90 top
NOREF#346  -  []  302.92 147.32 90 top
NOREF#347  -  []  229.21 246.34 0 top
NOREF#348  -  []  209.59 174.36 90 top
NOREF#349  -  []  511.59 276.41 90 top
NOREF#350  -  []  398.65 241.11 0 top
NOREF#351  -  []  326.43 288.41 90 top
NOREF#352  -  []  271.04 189.18 0 top
NOREF#353  -  []  128.24 171.1 0 top
NOREF#354  -  []  260.74 135.19 90 top
NOREF#355  -  []  397.55 209.41 90 top
NOREF#356  -  []  369.63 273.11 0 top
NOREF#357  -  []  166.06 148.4 90 top
NOREF#358  -  []  352.25 181.69 0 top
NOREF#359  -  []  230.73 186.66 0 top
NOREF#360  -  []  301.56 231.46 0 top
NOREF#361  -  []  401.89 180.15 0 top
NOREF#362  -  []  459.24 175.86 0 top
NOREF#363  -  []  387.39 297.12 0 top
NOREF#364  -  []  184.89 227.17 90 top
NOREF#365  -  []  229.51 183.41 0 top
NOREF#366  -  []  127.95 187.53 0 top
NOREF#367  -  []  371.48 241.11 0 top
NOREF#368  -  []  209.23 246.08 90 top
NOREF#369  -  []  385.19 265.11 0 top
NOREF#370  -  []  373.68 249.11 0 top
NOREF#371  -  []  271.34 182.64 0 top
NOREF#372  -  []  390.94 224.9 90 top
NOREF#373  -  []  473.6 206.05 90 top
NOREF#374  -  []  367.13 271.21 0 top
NOREF#375  -  []  112.41 214.71 0 top
NOREF#376  -  []  414.82 249.11 0 top
NOREF#377  -  []  167.7 145.93 90 top
NOREF#378  -  []  310.43 194.01 0 top
NOREF#379  -  []  304.82 146.05 0 top
NOREF#380  -  []  394.05 255.47 0 top
NOREF#381  -  []  105.83 190.55 90 top
NOREF#382  -  []  405.93 240.56 90 top
NOREF#383  -  []  332.51 265.56 0 top
NOREF#384  -  []  419.47 273.37 90 top
NOREF#385  -  []  302.11 180.71 0 top
NOREF#386  -  []  256.73 132.14 0 top
NOREF#387  -  []  303.15 271.32 90 top
NOREF#388  -  []  262.04 224.72 0 top
NOREF#389  -  []  367.48 242.38 90 top
NOREF#390  -  []  351.83 288.91 90 top
NOREF#391  -  []  369.63 289.12 0 top
NOREF#392  -  []  387.39 281.11 0 top
NOREF#393  -  []  101.82 273.87 90 top
NOREF#394  -  []  383.73 198.08 90 top
NOREF#395  -  []  221.56 171.46 0 top
NOREF#396  -  []  330.74 164.74 0 top
NOREF#397  -  []  369.63 289.12 0 top
NOREF#398  -  []  375.73 194.78 90 top
NOREF#399  -  []  339.33 205.56 90 top
NOREF#400  -  []  185.2 276.04 90 top
NOREF#401  -  []  259.33 265.56 0 top
NOREF#402  -  []  329.28 165.04 90 top
NOREF#403  -  []  166.06 216.47 90 top
NOREF#404  -  []  209.23 230.17 90 top
NOREF#405  -  []  230.43 249.52 0 top
NOREF#406  -  []  221.56 179.06 0 top
NOREF#407  -  []  228.36 202.16 45 top
NOREF#408  -  []  352.24 189.18 90 top
NOREF#409  -  []  261.63 195.43 90 top
NOREF#410  -  []  460.93 225.6 90 top
NOREF#411  -  []  199.59 171.96 90 top
NOREF#412  -  []  175.7 246.08 90 top
NOREF#413  -  []  463.61 214.96 0 top
NOREF#414  -  []  230.43 193.37 90 top
NOREF#415  -  []  184.47 176.66 90 top
NOREF#416  -  []  318.45 197.01 0 top
NOREF#417  -  []  184.47 200.54 0 top
NOREF#418  -  []  310.41 193.37 90 top
NOREF#419  -  []  296.96 192.14 0 top
NOREF#420  -  []  518.38 290.38 90 top
NOREF#421  -  []  339.46 288.86 90 top
NOREF#422  -  []  453.88 171.53 0 top
NOREF#423  -  []  451.68 239.34 0 top
NOREF#424  -  []  199.59 189.04 90 top
NOREF#425  -  []  273.81 286.96 90 top
NOREF#426  -  []  209.23 218.65 90 top
NOREF#427  -  []  248 286.96 0 top
NOREF#428  -  []  253.72 264.65 90 top
NOREF#429  -  []  419.47 241.11 90 top
NOREF#430  -  []  271.04 242.96 0 top
NOREF#431  -  []  301.56 182.89 0 top
NOREF#432  -  []  237.2 296.61 0 top
NOREF#433  -  []  310.43 193.37 90 top
NOREF#434  -  []  385.19 241.11 0 top
NOREF#435  -  []  272.24 189.18 90 top
NOREF#436  -  []  369.38 257.11 0 top
NOREF#437  -  []  229.21 187.61 0 top
NOREF#438  -  []  253.33 181.33 90 top
NOREF#439  -  []  168.13 186.02 90 top
NOREF#440  -  []  84.04 290.38 90 top
NOREF#441  -  []  412.79 209.16 90 top
NOREF#442  -  []  222.11 192.14 0 top
NOREF#443  -  []  331.05 205.86 90 top
NOREF#444  -  []  201.23 247.18 90 top
NOREF#445  -  []  329.28 223.82 90 top
NOREF#446  -  []  177.33 201.29 90 top
NOREF#447  -  []  128.05 273.87 90 top
NOREF#448  -  []  253.4 264.35 90 top
NOREF#449  -  []  414.57 265.37 0 top
NOREF#450  -  []  229.51 193.69 0 top
NOREF#451  -  []  272.24 241.05 90 top
NOREF#452  -  []  456.04 222.5 0 top
NOREF#453  -  []  450.03 166.93 0 top
NOREF#454  -  []  223.56 245.29 90 top
NOREF#455  -  []  406.52 131.89 90 top
NOREF#456  -  []  253.4 265.56 90 top
NOREF#457  -  []  390.94 289.17 90 top
NOREF#458  -  []  368.28 297.12 0 top
NOREF#459  -  []  251.62 265.56 0 top
NOREF#460  -  []  317.66 224.72 0 top
NOREF#461  -  []  300.01 288.31 90 top
NOREF#462  -  []  262.36 296.86 0 top
NOREF#463  -  []  481.96 273.87 90 top
NOREF#464  -  []  378.33 209.11 0 top
NOREF#465  -  []  115.19 128.27 0 top
NOREF#466  -  []  423.61 188.92 90 top
NOREF#467  -  []  115.87 175.44 90 top
NOREF#468  -  []  419.9 240.56 90 top
NOREF#469  -  []  352.24 184.86 90 top
NOREF#470  -  []  262.04 164.74 0 top
NOREF#471  -  []  368.03 232.6 0 top
NOREF#472  -  []  251.05 205.86 90 top
NOREF#473  -  []  237.66 224.74 0 top
NOREF#474  -  []  250.5 288.86 0 top
NOREF#475  -  []  381.2 290.39 90 top
NOREF#476  -  []  412.62 289.12 0 top
NOREF#477  -  []  392.47 240.56 90 top
NOREF#478  -  []  330.73 265.55 0 top
NOREF#479  -  []  175.8 187.82 90 top
NOREF#480  -  []  230.41 183.09 90 top
NOREF#481  -  []  415.61 183.52 90 top
NOREF#482  -  []  395.67 133.16 90 top
NOREF#483  -  []  379.48 222.7 90 top
NOREF#484  -  []  192.47 195.52 90 top
NOREF#485  -  []  182.82 257.62 90 top
NOREF#486  -  []  165.8 144.78 0 top
NOREF#487  -  []  411.52 146.33 90 top
NOREF#488  -  []  485.36 289.48 90 top
NOREF#489  -  []  333.33 181.33 90 top
NOREF#490  -  []  352.24 182.32 90 top
NOREF#491  -  []  167.7 214 90 top
NOREF#492  -  []  410.78 131.89 0 top
NOREF#493  -  []  246.67 288.16 90 top
NOREF#494  -  []  230.43 186.34 90 top
NOREF#495  -  []  113.08 129.54 0 top
NOREF#496  -  []  328.96 164.72 0 top
NOREF#497  -  []  217.41 273.24 0 top
NOREF#498  -  []  328.96 164.74 0 top
NOREF#499  -  []  287.91 280.1 0 top
NOREF#500  -  []  317.98 165.04 90 top
NOREF#501  -  []  501.87 273.87 90 top
NOREF#502  -  []  329.85 224.72 0 top
NOREF#503  -  []  199.33 240.28 0 top
NOREF#504  -  []  395.2 265.37 0 top
NOREF#505  -  []  241.6 296.61 0 top
NOREF#506  -  []  222.11 180.71 0 top
NOREF#507  -  []  182.82 230.19 90 top
NOREF#508  -  []  331.62 205.56 0 top
NOREF#509  -  []  210.6 255.9 90 top
NOREF#510  -  []  127.55 191.95 90 top
NOREF#511  -  []  167.7 147.28 90 top
NOREF#512  -  []  401.89 163.64 0 top
NOREF#513  -  []  284.79 272.65 90 top
NOREF#514  -  []  381.2 226.12 90 top
NOREF#515  -  []  184.47 186.57 0 top
NOREF#516  -  []  456.08 195.91 0 top
NOREF#517  -  []  115.61 191.95 0 top
NOREF#518  -  []  201.66 240.88 90 top
NOREF#519  -  []  271.34 183.91 0 top
NOREF#520  -  []  302.11 252.14 0 top
NOREF#521  -  []  263.63 165.04 90 top
NOREF#522  -  []  310.41 188.88 90 top
NOREF#523  -  []  424.47 163.19 90 top
NOREF#524  -  []  253.4 204.35 90 top
NOREF#525  -  []  388.43 163.64 0 top
NOREF#526  -  []  404.24 146.88 0 top
NOREF#527  -  []  167.7 186.57 90 top
NOREF#528  -  []  185.2 292.55 90 top
NOREF#529  -  []  377.23 257.16 90 top
NOREF#530  -  []  295.96 237.06 0 top
NOREF#531  -  []  101.82 271.33 90 top
NOREF#532  -  []  401.89 180.15 0 top
NOREF#533  -  []  259.33 265.55 0 top
NOREF#534  -  []  192.47 162.1 90 top
NOREF#535  -  []  352.25 242.96 0 top
NOREF#536  -  []  339.65 204.65 90 top
NOREF#537  -  []  392.24 196.98 90 top
NOREF#538  -  []  310.73 246.66 0 top
NOREF#539  -  []  175.7 135.17 90 top
NOREF#540  -  []  252.51 265.55 0 top
NOREF#541  -  []  229.51 186.66 0 top
NOREF#542  -  []  192.47 205.19 90 top
NOREF#543  -  []  247.57 264.65 90 top
NOREF#544  -  []  231.15 159.63 90 top
NOREF#545  -  []  192.47 154.88 90 top
NOREF#546  -  []  328.33 247.93 0 top
NOREF#547  -  []  272.24 242.32 90 top
NOREF#548  -  []  459.24 219.3 90 top
NOREF#549  -  []  175.8 133.97 90 top
NOREF#550  -  []  424.47 163.09 90 top
NOREF#551  -  []  252.6 296.86 0 top
NOREF#552  -  []  322.23 233.13 90 top
NOREF#553  -  []  251.06 223.82 90 top
NOREF#554  -  []  199.33 199.39 0 top
NOREF#555  -  []  101.29 247.16 90 top
NOREF#556  -  []  250.73 205.56 0 top
NOREF#557  -  []  419.9 272.82 90 top
NOREF#558  -  []  375.22 180.15 0 top
NOREF#559  -  []  168.13 227.17 90 top
NOREF#560  -  []  230.43 193.37 90 top
NOREF#561  -  []  301.56 171.46 0 top
NOREF#562  -  []  182.57 158.5 0 top
NOREF#563  -  []  352.25 189.18 90 top
NOREF#564  -  []  413.71 148.15 90 top
NOREF#565  -  []  327.25 265.55 0 top
NOREF#566  -  []  342.68 164.74 90 top
NOREF#567  -  []  410.52 289.12 0 top
NOREF#568  -  []  192.47 216.45 90 top
NOREF#569  -  []  175.7 191.22 90 top
NOREF#570  -  []  247.25 265.55 0 top
NOREF#571  -  []  272.24 184.86 90 top
NOREF#572  -  []  217.71 276.09 0 top
NOREF#573  -  []  391.96 131.89 0 top
NOREF#574  -  []  396.55 241.11 0 top
NOREF#575  -  []  263.71 288.86 0 top
NOREF#576  -  []  199.59 145.03 0 top
NOREF#577  -  []  230.43 188.88 0 top
NOREF#578  -  []  295.96 248.49 0 top
NOREF#579  -  []  424.98 146.43 90 top
NOREF#580  -  []  336.45 224.74 0 top
NOREF#581  -  []  420.15 131.34 90 top
NOREF#582  -  []  286.12 288.86 90 top
NOREF#583  -  []  384.59 162.94 90 top
NOREF#584  -  []  272.55 249.5 0 top
NOREF#585  -  []  385.19 257.11 0 top
NOREF#586  -  []  377.32 163.39 0 top
NOREF#587  -  []  35.83 132.61 0 top
NOREF#588  -  []  184.47 173.11 0 top
NOREF#589  -  []  385.93 178.25 0 top
NOREF#590  -  []  330.18 182.88 0 top
NOREF#591  -  []  218.13 214.06 90 top
NOREF#592  -  []  385.61 208.56 90 top
NOREF#593  -  []  301.95 290.13 90 top
NOREF#594  -  []  317.98 225.04 90 top
NOREF#595  -  []  184.47 206.29 90 top
NOREF#596  -  []  295.96 188.49 0 top
NOREF#597  -  []  175.8 242.68 90 top
NOREF#598  -  []  463.61 179.15 0 top
NOREF#599  -  []  378.75 224.05 90 top
NOREF#600  -  []  172.08 291.65 90 top
NOREF#601  -  []  330.51 288.86 0 top
NOREF#602  -  []  319.33 243.63 90 top
NOREF#603  -  []  419.9 272.92 90 top
NOREF#604  -  []  182.82 243.9 90 top
NOREF#605  -  []  259.33 204.35 90 top
NOREF#606  -  []  355.89 130.17 90 top
NOREF#607  -  []  167.7 165.4 90 top
NOREF#608  -  []  461.96 174.55 0 top
NOREF#609  -  []  405.17 131.89 0 top
NOREF#610  -  []  254.29 204.35 90 top
NOREF#611  -  []  346.27 135.17 90 top
NOREF#612  -  []  310.43 247.61 90 top
NOREF#613  -  []  403.41 209.61 0 top
NOREF#614  -  []  332.51 265.55 0 top
NOREF#615  -  []  392.47 272.66 90 top
NOREF#616  -  []  343.95 224.74 90 top
NOREF#617  -  []  407.67 129.99 90 top
NOREF#618  -  []  107.02 179.19 0 top
NOREF#619  -  []  250.73 265.56 90 top
NOREF#620  -  []  398.65 297.12 0 top
NOREF#621  -  []  314.92 144.15 90 top
NOREF#622  -  []  451.68 230.2 0 top
NOREF#623  -  []  302.32 144.15 0 top
NOREF#624  -  []  230.43 193.37 0 top
NOREF#625  -  []  408.02 287.22 0 top
NOREF#626  -  []  182.82 203.01 90 top
NOREF#627  -  []  101.82 287.84 90 top
NOREF#628  -  []  403.41 209.61 0 top
NOREF#629  -  []  175.8 160.9 90 top
NOREF#630  -  []  299.81 273.69 90 top
NOREF#631  -  []  477.24 195.66 0 top
NOREF#632  -  []  470.71 227 90 top
NOREF#633  -  []  463.61 171.53 0 top
NOREF#634  -  []  339.97 264.35 90 top
NOREF#635  -  []  459.28 211.76 0 top
NOREF#636  -  []  298.13 274.06 0 top
NOREF#637  -  []  379 288.57 90 top
NOREF#638  -  []  215.96 188.49 0 top
NOREF#639  -  []  184.47 178.86 90 top
NOREF#640  -  []  369.38 224.6 0 top
NOREF#641  -  []  175.7 209.49 90 top
NOREF#642  -  []  282.9 147.38 0 top
NOREF#643  -  []  403.99 188.15 0 top
NOREF#644  -  []  425.23 180.72 90 top
NOREF#645  -  []  303.56 245.29 90 top
NOREF#646  -  []  177.33 228.47 90 top
NOREF#647  -  []  400.85 249.11 0 top
NOREF#648  -  []  177.33 173.86 90 top
NOREF#649  -  []  352.24 244.86 90 top
NOREF#650  -  []  400.25 148.15 90 top
NOREF#651  -  []  511.59 291.28 90 top
NOREF#652  -  []  283.21 282 0 top
NOREF#653  -  []  184.47 161 90 top
NOREF#654  -  []  332.83 264.65 90 top
NOREF#655  -  []  326.23 233.13 0 top
NOREF#656  -  []  230.43 243.09 90 top
NOREF#657  -  []  471.21 211.76 0 top
NOREF#658  -  []  175.7 202.99 90 top
NOREF#659  -  []  305.94 296.86 0 top
NOREF#660  -  []  199.59 230.19 90 top
NOREF#661  -  []  167.7 256.5 90 top
NOREF#662  -  []  108.27 178.64 0 top
NOREF#663  -  []  372.72 161.49 0 top
NOREF#664  -  []  352.55 245.18 0 top
NOREF#665  -  []  251.05 204.65 90 top
NOREF#666  -  []  119.99 214.79 0 top
NOREF#667  -  []  184.47 255.15 0 top
NOREF#668  -  []  352.25 183.59 90 top
NOREF#669  -  []  251.38 163.52 90 top
NOREF#670  -  []  252.6 288.86 0 top
NOREF#671  -  []  380.59 222.95 0 top
NOREF#672  -  []  342.04 164.72 0 top
NOREF#673  -  []  376.98 257.11 0 top
NOREF#674  -  []  405.5 241.11 90 top
NOREF#675  -  []  375.73 199.18 90 top
NOREF#676  -  []  336.77 163.82 90 top
NOREF#677  -  []  165.8 240.28 0 top
NOREF#678  -  []  22.16 130.26 90 top
NOREF#679  -  []  221.56 182.89 0 top
NOREF#680  -  []  392.24 199.18 90 top
NOREF#681  -  []  327.25 205.56 90 top
NOREF#682  -  []  270.04 280.1 0 top
NOREF#683  -  []  392.47 256.56 90 top
NOREF#684  -  []  175.7 250.38 90 top
NOREF#685  -  []  253.53 140.14 0 top
NOREF#686  -  []  495.08 277.31 90 top
NOREF#687  -  []  259.65 204.65 90 top
NOREF#688  -  []  412.62 241.11 0 top
NOREF#689  -  []  339.33 205.56 0 top
NOREF#690  -  []  201.66 227.17 90 top
NOREF#691  -  []  410.52 241.11 0 top
NOREF#692  -  []  473.79 239.64 0 top
NOREF#693  -  []  352.25 249.18 90 top
NOREF#694  -  []  167.7 145.93 0 top
NOREF#695  -  []  314.2 145.6 90 top
NOREF#696  -  []  380.59 255.21 0 top
NOREF#697  -  []  334.61 205.86 90 top
NOREF#698  -  []  188.08 291.65 90 top
NOREF#699  -  []  343.63 165.04 90 top
NOREF#700  -  []  459.24 219.3 0 top
NOREF#701  -  []  415.61 185.72 90 top
NOREF#702  -  []  394.66 274.38 90 top
NOREF#703  -  []  209.49 155.13 90 top
NOREF#704  -  []  415.1 163.64 0 top
NOREF#705  -  []  201.49 147.53 90 top
NOREF#706  -  []  387.39 265.11 0 top
NOREF#707  -  []  184.47 163.2 90 top
NOREF#708  -  []  312.42 146.05 0 top
NOREF#709  -  []  310.41 246.34 90 top
NOREF#710  -  []  373.68 232.6 0 top
NOREF#711  -  []  351.04 249.82 0 top
NOREF#712  -  []  495.08 259.9 90 top
NOREF#713  -  []  201.23 241.43 0 top
NOREF#714  -  []  185.2 273.5 90 top
NOREF#715  -  []  247.89 264.35 90 top
NOREF#716  -  []  390.69 273.11 0 top
NOREF#717  -  []  230.43 187.61 90 top
NOREF#718  -  []  333.72 204.65 90 top
NOREF#719  -  []  127.95 222.33 0 top
NOREF#720  -  []  251.05 264.65 90 top
NOREF#721  -  []  475.04 239.09 0 top
NOREF#722  -  []  248.96 224.72 0 top
NOREF#723  -  []  411.52 146.43 90 top
NOREF#724  -  []  224.65 271.67 0 top
NOREF#725  -  []  384.17 180.15 90 top
NOREF#726  -  []  418.37 241.16 90 top
NOREF#727  -  []  107.76 238.84 0 top
NOREF#728  -  []  465.81 179.15 0 top
NOREF#729  -  []  388.43 146.88 0 top
NOREF#730  -  []  381.2 242.38 90 top
NOREF#731  -  []  483.17 130.26 90 top
NOREF#732  -  []  329.6 163.52 90 top
NOREF#733  -  []  167.7 165.4 90 top
NOREF#734  -  []  352.24 189.18 90 top
NOREF#735  -  []  66.26 290.38 90 top
NOREF#736  -  []  418.12 241.11 0 top
NOREF#737  -  []  320.83 254.63 0 top
NOREF#738  -  []  107.02 166.42 90 top
NOREF#739  -  []  459.28 168.33 0 top
NOREF#740  -  []  348.28 296.86 0 top
NOREF#741  -  []  184.47 178.86 90 top
NOREF#742  -  []  511.59 257.36 90 top
NOREF#743  -  []  300.36 177.06 0 top
NOREF#744  -  []  310.73 249.2 0 top
NOREF#745  -  []  194.09 242.18 90 top
NOREF#746  -  []  409.49 163.64 0 top
NOREF#747  -  []  398.65 249.11 0 top
NOREF#748  -  []  398.65 281.11 0 top
NOREF#749  -  []  528.1 273.87 90 top
NOREF#750  -  []  305.94 288.86 0 top
NOREF#751  -  []  331.94 265.86 90 top
NOREF#752  -  []  336.45 164.72 0 top
NOREF#753  -  []  399.07 208.81 90 top
NOREF#754  -  []  201.49 159.65 90 top
NOREF#755  -  []  310.41 187.61 90 top
NOREF#756  -  []  182.57 226.57 0 top
NOREF#757  -  []  511.59 273.87 90 top
NOREF#758  -  []  351.34 189.5 0 top
NOREF#759  -  []  337.09 224.74 90 top
NOREF#760  -  []  327.25 204.35 90 top
NOREF#761  -  []  250.17 225.04 90 top
NOREF#762  -  []  124.35 195.15 0 top
NOREF#763  -  []  260.83 174.63 90 top
NOREF#764  -  []  199.59 158.5 0 top
NOREF#765  -  []  417.87 257.37 0 top
NOREF#766  -  []  351.04 249.18 0 top
NOREF#767  -  []  167.7 260.9 90 top
NOREF#768  -  []  352.25 244.23 0 top
NOREF#769  -  []  184.47 192.32 90 top
NOREF#770  -  []  396.22 139.89 0 top
NOREF#771  -  []  459.28 227 0 top
NOREF#772  -  []  200.98 258.7 90 top
NOREF#773  -  []  250.73 205.55 0 top
NOREF#774  -  []  321.35 296.86 0 top
NOREF#775  -  []  284.36 272.1 90 top
NOREF#776  -  []  250.49 164.74 90 top
NOREF#777  -  []  167.7 227.72 0 top
NOREF#778  -  []  199.84 175.58 90 top
NOREF#779  -  []  384.17 163.39 90 top
NOREF#780  -  []  330.49 224.74 90 top
NOREF#781  -  []  200.98 256.5 90 top
NOREF#782  -  []  351.34 249.5 0 top
NOREF#783  -  []  330.49 164.74 90 top
NOREF#784  -  []  230.73 189.2 0 top
NOREF#785  -  []  230.73 253.69 0 top
NOREF#786  -  []  405.5 225.11 90 top
NOREF#787  -  []  194.09 173.86 90 top
NOREF#788  -  []  332.51 204.35 90 top
NOREF#789  -  []  194.09 255.9 90 top
NOREF#790  -  []  381.74 265.11 0 top
NOREF#791  -  []  286.81 272.1 0 top
NOREF#792  -  []  351.34 181.37 0 top
NOREF#793  -  []  322.23 173.13 0 top
NOREF#794  -  []  334.61 204.65 90 top
NOREF#795  -  []  168.69 276.04 90 top
NOREF#796  -  []  332.83 265.86 90 top
NOREF#797  -  []  299.81 213.69 90 top
NOREF#798  -  []  331.54 252.73 90 top
NOREF#799  -  []  175.7 232.37 90 top
NOREF#800  -  []  220.36 177.06 0 top
NOREF#801  -  []  252.83 264.65 90 top
NOREF#802  -  []  395.2 297.12 0 top
NOREF#803  -  []  398.53 161.74 90 top
NOREF#804  -  []  366.88 239.21 0 top
NOREF#805  -  []  297.71 276.09 0 top
NOREF#806  -  []  230.73 249.2 0 top
NOREF#807  -  []  294.94 296.86 0 top
NOREF#808  -  []  314.19 145.5 90 top
NOREF#809  -  []  462.06 277.31 90 top
NOREF#810  -  []  393.19 222.95 90 top
NOREF#811  -  []  263.2 232.26 90 top
NOREF#812  -  []  309.21 183.09 0 top
NOREF#813  -  []  410.52 273.37 0 top
NOREF#814  -  []  109.96 238.84 0 top
NOREF#815  -  []  201.49 149.73 90 top
NOREF#816  -  []  199.59 145.03 90 top
NOREF#817  -  []  208.98 257.6 90 top
NOREF#818  -  []  259.33 265.55 0 top
NOREF#819  -  []  333.4 204.35 90 top
NOREF#820  -  []  118.45 239.39 0 top
NOREF#821  -  []  352.24 249.18 90 top
NOREF#822  -  []  384.36 131.89 0 top
NOREF#823  -  []  415.61 185.72 90 top
NOREF#824  -  []  166.06 203.01 90 top
NOREF#825  -  []  194.09 214.75 90 top
NOREF#826  -  []  394.66 290.39 90 top
NOREF#827  -  []  399.64 144.98 0 top
NOREF#828  -  []  271.34 189.5 0 top
NOREF#829  -  []  254.29 205.56 90 top
NOREF#830  -  []  258.61 131.69 90 top
NOREF#831  -  []  257.08 132.19 90 top
NOREF#832  -  []  397.38 180.15 90 top
NOREF#833  -  []  288.74 290.13 90 top
NOREF#834  -  []  378.75 256.56 90 top
NOREF#835  -  []  251.06 163.82 90 top
NOREF#836  -  []  104.18 191.95 0 top
NOREF#837  -  []  310.43 253.37 90 top
NOREF#838  -  []  96.58 195.15 0 top
NOREF#839  -  []  184.89 254.6 90 top
NOREF#840  -  []  252.83 205.86 90 top
NOREF#841  -  []  371.48 224.6 0 top
NOREF#842  -  []  266.49 143.19 0 top
NOREF#843  -  []  414.25 154.88 0 top
NOREF#844  -  []  218.16 188.49 0 top
NOREF#845  -  []  118.7 222.88 0 top
NOREF#846  -  []  288.14 286.96 0 top
NOREF#847  -  []  327.7 131.09 90 top
NOREF#848  -  []  272.25 244.86 90 top
NOREF#849  -  []  119.95 195.15 0 top
NOREF#850  -  []  261.63 255.43 90 top
NOREF#851  -  []  377.32 171.39 0 top
NOREF#852  -  []  425.7 144.98 90 top
NOREF#853  -  []  277.17 288.86 0 top
NOREF#854  -  []  410.27 257.37 0 top
NOREF#855  -  []  127.55 219.13 90 top
NOREF#856  -  []  167.7 244.98 90 top
NOREF#857  -  []  318.3 224.74 90 top
NOREF#858  -  []  225.83 204.31 0 top
NOREF#859  -  []  115.61 211.51 90 top
NOREF#860  -  []  392.66 192.88 90 top
NOREF#861  -  []  167.7 138.47 90 top
NOREF#862  -  []  450.03 182.17 0 top
NOREF#863  -  []  155.57 272.6 90 top
NOREF#864  -  []  404.4 273.16 90 top
NOREF#865  -  []  417.2 171.64 0 top
NOREF#866  -  []  376.23 209.11 0 top
NOREF#867  -  []  483.04 239.09 0 top
NOREF#868  -  []  390.69 241.11 0 top
NOREF#869  -  []  298.13 214.06 90 top
NOREF#870  -  []  411.26 179.6 90 top
NOREF#871  -  []  275.12 271.65 90 top
